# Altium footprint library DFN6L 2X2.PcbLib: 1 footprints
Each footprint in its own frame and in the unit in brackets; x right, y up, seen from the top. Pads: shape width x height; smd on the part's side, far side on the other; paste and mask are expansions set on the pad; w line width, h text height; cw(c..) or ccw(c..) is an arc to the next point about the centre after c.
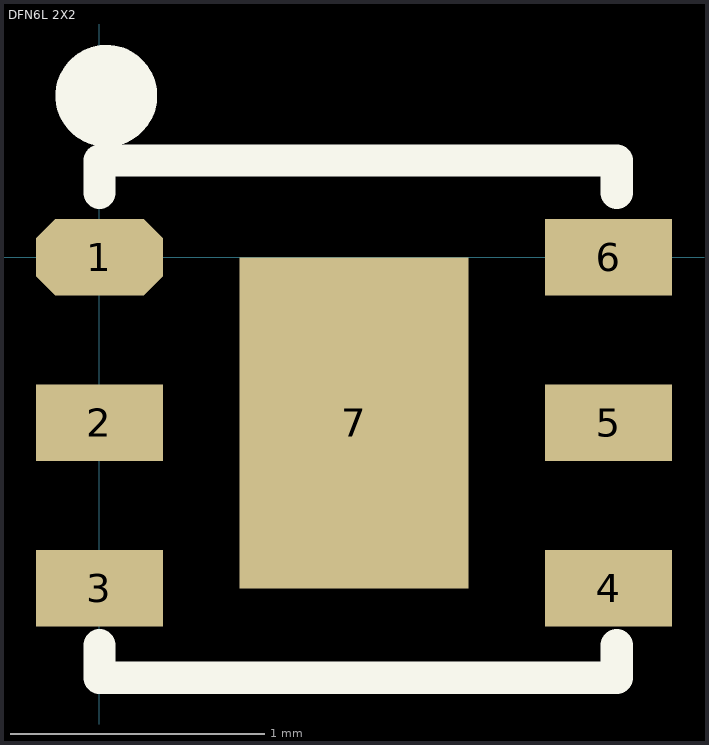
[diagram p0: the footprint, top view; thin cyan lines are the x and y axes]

## DFN6L 2X2 [mm]
pads (7):
  oct 0.5x0.3 smd: 1(0,0)
  rect 0.5x0.3 smd: 2(0,-0.65) 3(0,-1.3) 4(2,-1.3) 5(2,-0.65) 6(2,0)
  rect 0.9x1.3 smd: 7(1,-0.65)
Top Overlay:
  circle w0.2: c0.027,0.635 r0.1
  lines w0.127: 0,-1.524 0,-1.651 2.032,-1.651 2.032,-1.524 ; 0,0.254 0,0.381 2.032,0.381 2.032,0.254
